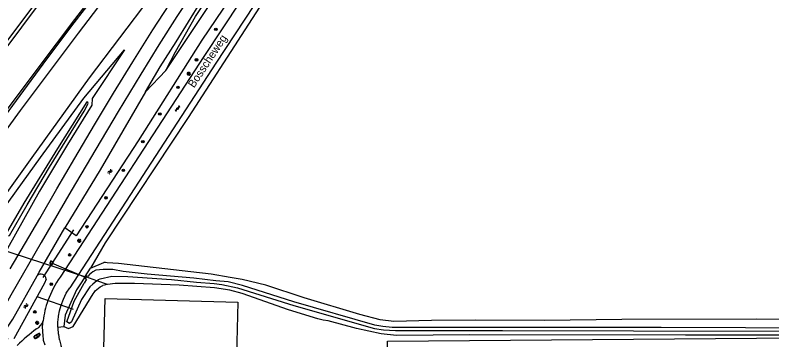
# Model space of a CAD drawing. Extents: x 137999 to 141000, y 397500 to 400501.
# Drawn here: x 138446.7 to 138683.2, y 398816.7 to 398918.2 of the extents above; entities that cross this region are included whole.
import ezdxf

# ---------------------------------------------------------------- set-up
doc = ezdxf.new("R2010")
doc.units = 0
for name, color, linetype in [('gg-anno-openbare ruimte label', 7, 'Continuous'), ('gg-knt-BGT kruinlijn', 7, 'Continuous'), ('gg-knt-bronhoudergrens', 7, 'Continuous'), ('gg-knt-verharding', 7, 'Continuous'), ('gg-knt-verharding nz', 7, 'Continuous'), ('gg-kntw-bovenkant insteek waterloop', 7, 'Continuous'), ('gg-kwrk-duiker nz buis', 7, 'Continuous'), ('gt-symb-boom', 7, 'Continuous'), ('gt-symb-gesloten verharding', 7, 'Continuous'), ('gt-symb-klinker verharding', 7, 'Continuous'), ('gt-symb-lichtmast', 7, 'Continuous'), ('gt-symb-rioolschacht', 7, 'Continuous'), ('gt-symb-watersymbool', 7, 'Continuous'), ('gx-grn-maaiveld', 7, 'Continuous')]:
    doc.layers.add(name, color=color, linetype=linetype)

# ---------------------------------------------------------------- blocks, each defined once
blk = doc.blocks.new('gt0-BOOM')
at = {"layer": 'gt-symb-boom'}
for radius in [0.4, 0.2]:
    blk.add_circle((0, 0), radius, dxfattribs=at)
blk = doc.blocks.new('gt0-GESVH1')
at = {"layer": 'gt-symb-gesloten verharding'}
for p, q in [((-0.99, -0.26), (0.01, 0.24)), ((0.01, -0.26), (-0.99, 0.24)), ((0.01, 0.24), (1.01, -0.26)), ((1.01, 0.24), (0.01, -0.26))]:
    blk.add_line(p, q, dxfattribs=at)
blk = doc.blocks.new('gt0-LMAST')
at = {"layer": 'gt-symb-lichtmast'}
for p, q in [((-0.18, 0.17), (-0.45, 0.44)), ((0, 0.25), (0, 0.62)), ((0.17, 0.17), (0.44, 0.44)), ((-0.25, 0), (-0.63, 0)), ((-0.18, -0.18), (-0.45, -0.45)), ((0, -0.25), (0, -0.63)), ((0.44, -0.45), (0.17, -0.18)), ((0.25, 0), (0.62, 0))]:
    blk.add_line(p, q, dxfattribs=at)
blk.add_circle((0, 0), 0.25, dxfattribs=at)
blk = doc.blocks.new('gt0-WA')
at = {"layer": 'gt-symb-watersymbool'}
for centre, start, end in [((-0.32, 0.02), 28.0725, 151.9275), ((0.43, 0.42), 208.0725, 331.9275), ((-0.32, -0.43), 28.0725, 151.9275), ((0.43, -0.03), 208.0725, 331.9275)]:
    blk.add_arc(centre, 0.425, start, end, dxfattribs=at)
blk = doc.blocks.new('gt0-RS')
at = {"layer": 'gt-symb-rioolschacht'}
blk.add_lwpolyline([(-0.5, -0.5), (0.5, -0.5), (0.5, 0.5), (-0.5, 0.5)], close=True, dxfattribs=at)
blk.add_circle((0, 0), 0.375, dxfattribs=at)
blk = doc.blocks.new('gt0-KL1')
at = {"layer": 'gt-symb-klinker verharding'}
for p, q in [((-1.15, 0.3), (1.15, 0.3)), ((-1, -0.3), (-1, 0.3)), ((-0.5, 0.3), (-0.5, 0.45)), ((0, -0.3), (0, 0.3)), ((0.5, 0.3), (0.5, 0.45)), ((1, -0.3), (1, 0.3)), ((-1.15, -0.3), (1.15, -0.3)), ((-0.5, -0.45), (-0.5, -0.3)), ((0.5, -0.45), (0.5, -0.3))]:
    blk.add_line(p, q, dxfattribs=at)

msp = doc.modelspace()

# ---------------------------------------------------------------- linework, layer by layer
at = {"layer": 'gg-knt-BGT kruinlijn'}
for p, q in [((138497.03, 398909.88), (138504.8, 398922.39)), ((138441.84, 398907.05), (138452.95, 398921.72)), ((138492, 398902.03), (138497.03, 398909.88)), ((138487.49, 398894.21), (138492, 398902.03))]:
    msp.add_line(p, q, dxfattribs=at)
at = {"layer": 'gg-knt-bronhoudergrens'}
msp.add_lwpolyline([(138453.6, 398836.7), (138454.22, 398837.81), (138462.27, 398851.67)], dxfattribs=at)
at = {"layer": 'gg-knt-verharding'}
for p, q in [((138453.68, 398818.43), (138452.83, 398817.95)), ((138453.33, 398817.19), (138454.18, 398817.72))]:
    msp.add_line(p, q, dxfattribs=at)
msp.add_lwpolyline([(138571.8, 399000), (138540.02, 398957.23), (138505.73, 398905.24), (138460.79, 398836.3)], dxfattribs=at)
for centre, radius, start, end in [((138485.43, 398818.82), 30.21, 144.6468, 160.3408), ((138485.42, 398818.82), 30.2, 160.3332, 172.7902), ((138451.65, 398823.67), 3.95, 296.1487, 344.4578), ((138493.04, 398768.15), 65.36, 127.3417, 134.273), ((138453.07, 398817.56), 0.454, 121.3269, 305.4573), ((138453.96, 398818.1), 0.435, 300.0104, 130.3422)]:
    msp.add_arc(centre, radius, start, end, dxfattribs=at)
at = {"layer": 'gg-knt-verharding nz'}
msp.add_lwpolyline([(138456.1, 398815.01), (138455.63, 398816.48), (138455.59, 398816.9), (138455.45, 398817.89), (138455.24, 398820.76), (138455.46, 398822.61)], dxfattribs=at)
at = {"layer": 'gg-kntw-bovenkant insteek waterloop'}
for points in [[(138569.06, 399000), (138567.59, 398998.16), (138559.63, 398990.84), (138557.55, 398988.03), (138505.1, 398910.32), (138485.15, 398878.9), (138465.82, 398849.17), (138462.27, 398851.67)], [(138444.52, 398816.88), (138442.67, 398818.18), (138446.06, 398823.16), (138453.6, 398836.7)], [(138456.41, 398835.69), (138455.87, 398834.38), (138446.37, 398816.98)]]:
    msp.add_lwpolyline(points, dxfattribs=at)
msp.add_arc((138454.79, 398835.61), 1.62, 3.0222, 137.6006, dxfattribs=at)
at = {"layer": 'gg-kwrk-duiker nz buis'}
for p, q in [((138398.36, 398859.43), (138468.99, 398836.26)), ((138455.47, 398836.15), (138465.1, 398851.11)), ((138458.09, 398840.75), (138468.78, 398836.21)), ((138465.02, 398826.16), (138453.59, 398830.17))]:
    msp.add_line(p, q, dxfattribs=at)
at = {"layer": 'gx-grn-maaiveld'}
for p, q in [((138487.49, 398894.21), (138493.8, 398900.86)), ((138470.28, 398839.08), (138474.43, 398840.89)), ((138468.57, 398836.44), (138467.34, 398834.55)), ((138468.85, 398836.34), (138468.57, 398836.44)), ((138472.26, 398835.13), (138468.85, 398836.34)), ((138472.26, 398835.13), (138471.06, 398834.07)), ((138475.64, 398833.94), (138472.26, 398835.13)), ((138475.64, 398833.94), (138474.1, 398833.68)), ((138460.08, 398820.65), (138461.99, 398820.81))]:
    msp.add_line(p, q, dxfattribs=at)
for points in [[(138501.93, 398981.31), (138473.35, 398946.25), (138454.53, 398922.28), (138436.97, 398898.82), (138420.73, 398876.2), (138406.46, 398855.7), (138389.11, 398830.38), (138374.16, 398808.03), (138357.61, 398782.41), (138337.09, 398749.31), (138322.84, 398725.57), (138306.14, 398696.86), (138294.74, 398676.9)], [(138511.96, 398975.93), (138501.93, 398963.57), (138488.51, 398946.76), (138477.26, 398932.48), (138465.23, 398916.8), (138454.1, 398902.02), (138442.39, 398886.25), (138431.73, 398871.47), (138423.79, 398860.21), (138409, 398839.04), (138400.22, 398826.26), (138391.06, 398812.74), (138383.32, 398801.2), (138369.25, 398779.46), (138351.53, 398751.27), (138335.99, 398725.63), (138320.07, 398698.46), (138305.76, 398673.14), (138304.77, 398671.25)], [(138305.51, 398670.84), (138318.83, 398694.74), (138335.5, 398723.24), (138353.01, 398752.39), (138371.79, 398782.1), (138383.87, 398800.92), (138391.62, 398812.28), (138401.25, 398826.65), (138409.13, 398838.16), (138419.71, 398853.23), (138427.79, 398864.74), (138439.06, 398880.6), (138447.18, 398891.55), (138456.66, 398904.44), (138465.19, 398915.76), (138474.86, 398928.37), (138485.07, 398941.42), (138495.05, 398953.91), (138502.76, 398963.65), (138512.45, 398975.67)], [(138515.33, 398974.12), (138508.14, 398965.28), (138499.1, 398954.3), (138490.91, 398943.97), (138482.68, 398933.64), (138474.18, 398922.64), (138466.42, 398912.51), (138457.95, 398901.32), (138448.31, 398888.42), (138439.64, 398876.56), (138431.08, 398864.56), (138422.11, 398851.79), (138414.01, 398840.2), (138403.68, 398825.33), (138393.35, 398810.12), (138386.42, 398799.63), (138373.52, 398779.54), (138349.79, 398741.53), (138323.85, 398697.93), (138308.01, 398669.51)], [(138445.2, 398838.89), (138454.46, 398854.65), (138459.76, 398863.94), (138465.34, 398873.45), (138471.5, 398883.92), (138477.49, 398893.83), (138483.55, 398903.63), (138489.79, 398913.61), (138496.63, 398924.24), (138502.81, 398933.7), (138510, 398944), (138515.54, 398951.76), (138520.63, 398958.64), (138518.24, 398960.23), (138506.25, 398945.82), (138488.86, 398923.75), (138469.91, 398898.56), (138451.9, 398873.72), (138435.15, 398850.39)], [(138536.45, 398944.23), (138509.39, 398903.14), (138463.79, 398832.99)], [(138538.48, 398944.62), (138500.76, 398886.17), (138474.86, 398846.97), (138470.28, 398839.08)], [(138493.8, 398900.86), (138496.8, 398906.75), (138503.12, 398917.76), (138509.47, 398927.48), (138512.14, 398931.65), (138515.98, 398937.39), (138519.12, 398939.39)], [(138493.8, 398900.86), (138508.22, 398922.45), (138519.12, 398939.39)], [(138510.93, 398938.07), (138503.76, 398927.52), (138497.3, 398917.73), (138491.67, 398908.92), (138485.99, 398899.71), (138478.97, 398888.11), (138471.93, 398876.34), (138464.28, 398863.27), (138454.82, 398847.09), (138445.4, 398830.65), (138437.66, 398816.93), (138433.16, 398808.86)], [(138319.3, 398663.29), (138320.07, 398664.67), (138327.85, 398678.47), (138336.64, 398694.05), (138345.76, 398709.35), (138356.08, 398726.35), (138365.52, 398742.12), (138375.87, 398758.54), (138387.56, 398776.99), (138398.34, 398793.59), (138411.58, 398813.08), (138429.8, 398839.31), (138439.07, 398852.14), (138454.7, 398873.68), (138468.19, 398892.19), (138480.86, 398907.3), (138470.85, 398892.13), (138470.73, 398890.07), (138463.09, 398877.71), (138454.36, 398863.15), (138444.37, 398845.19), (138441.69, 398841)], [(138487.49, 398894.21), (138473.34, 398869.79), (138462.27, 398851.67)], [(138468.29, 398888.14), (138469.6, 398890.53), (138469.4, 398890.9), (138469.15, 398891.04), (138459.97, 398876.54), (138449.41, 398859.44), (138443.92, 398849.96), (138444.13, 398849.45), (138444.45, 398849.24), (138444.92, 398849.29), (138450.49, 398858.84), (138457.51, 398870.62), (138468.29, 398888.14)], [(138468.57, 398836.44), (138468.57, 398836.44), (138470.28, 398839.08)], [(138709.84, 398822.76), (138678.4, 398823.13), (138636.32, 398823.04), (138612.17, 398822.78), (138590.49, 398822.81), (138576.79, 398822.72), (138565.07, 398822.41), (138560.83, 398822.9), (138554.47, 398824.65), (138537.09, 398829.84), (138525.08, 398833.78), (138517.68, 398835.54), (138513.96, 398836.2), (138507.98, 398837.26), (138501.66, 398837.9), (138478.99, 398840.51), (138475.46, 398840.79)], [(138701.3, 398820.36), (138648.59, 398820.54), (138601.81, 398820.59), (138564.58, 398820.55), (138561.57, 398820.81), (138559.12, 398821.26), (138533.82, 398828.59), (138517.77, 398833.64), (138513.32, 398834.83), (138509.43, 398835.18), (138502.58, 398835.94), (138487.95, 398837.26), (138480.53, 398838.02), (138477.28, 398838.65), (138474.24, 398838.71), (138471.96, 398838.51), (138471.02, 398837.98), (138470.01, 398837.16), (138469.47, 398836.51), (138469.08, 398836.73), (138468.85, 398836.34)], [(138792.19, 398837.02), (138789.69, 398836.25), (138782.84, 398833.81), (138771.64, 398830.41), (138752.15, 398825.35), (138742.61, 398823), (138723.68, 398818.94), (138718.46, 398818.15), (138656.21, 398818.1), (138588.8, 398818.22), (138565.84, 398818.04), (138561.1, 398818.52), (138553.4, 398820.2), (138544.56, 398822.59), (138543.01, 398822.89), (138541.31, 398823.22), (138532.12, 398826.1), (138517.7, 398831.22), (138513.81, 398832.21), (138509.07, 398832.97), (138497.98, 398833.8), (138484.06, 398834.27), (138477.98, 398834.33), (138475.64, 398833.94)], [(138467.34, 398834.55), (138465.9, 398832.34), (138462.4, 398824.36), (138461.99, 398820.81)], [(138471.06, 398834.07), (138470.11, 398833.24), (138467.46, 398829.32), (138464.32, 398822.3), (138463.68, 398821.8), (138462.86, 398822.35), (138465.19, 398828.82), (138468.32, 398834.43)], [(138468.85, 398836.34), (138468.78, 398836.21), (138468.64, 398835.94), (138469.02, 398835.68), (138468.32, 398834.43)], [(138472.26, 398835.13), (138472.5, 398835.34), (138472.8, 398835.51), (138473.33, 398835.81), (138476.93, 398836.6), (138481.95, 398836.52), (138495.6, 398835.51), (138503.35, 398834.75), (138508.93, 398834.25), (138511.34, 398833.94), (138516.16, 398832.9), (138533.76, 398827.4), (138559.06, 398820.26), (138561.84, 398819.84), (138565.58, 398819.59), (138598.97, 398819.6), (138639.89, 398819.52), (138700.99, 398819.36)], [(138461.07, 398827.54), (138461.8, 398829.45), (138462.71, 398831.27), (138463.79, 398832.99)], [(138461.99, 398820.81), (138463.44, 398820.22), (138464.9, 398820.9), (138471.12, 398831.07), (138471.38, 398831.5), (138471.7, 398832.05), (138473.25, 398833.26), (138474.1, 398833.68)], [(138474.83, 398829.58), (138516.36, 398828.47), (138515.47, 398795.14), (138473.99, 398798.55), (138474.83, 398829.58)], [(138460.08, 398820.65), (138460.08, 398822.05), (138460.08, 398822.15), (138460.09, 398822.23), (138460.24, 398823.86), (138460.25, 398823.98), (138460.27, 398824.04), (138460.57, 398825.73), (138460.58, 398825.78), (138460.59, 398825.8), (138461.07, 398827.54)], [(138460.08, 398820.65), (138460.08, 398820.32), (138460.22, 398818.61), (138460.23, 398818.49), (138460.25, 398818.41), (138460.53, 398816.78), (138460.55, 398816.69), (138460.56, 398816.64), (138461.01, 398814.98), (138461.02, 398814.92), (138461.04, 398814.89), (138461.65, 398813.2)], [(138563.1, 398809.75), (138563.04, 398816.25), (138729.56, 398817.68), (138757.71, 398817.87), (138757.64, 398822.29), (138789.96, 398822.44), (138789.89, 398809.11), (138793.97, 398809.15), (138794.28, 398758.6), (138730.04, 398758.64), (138642.09, 398757.88), (138642.08, 398758.73), (138570.05, 398758.11), (138570.04, 398759.5), (138563.46, 398759.45), (138563.35, 398772.44), (138552.04, 398772.34), (138551.72, 398809.65), (138563.1, 398809.75)]]:
    msp.add_lwpolyline(points, dxfattribs=at)
msp.add_arc((138474.17, 398833.22), 7.68, 80.3193, 88.0839, dxfattribs=at)

# ---------------------------------------------------------------- block references
at = {"layer": 'gt-symb-boom'}
for p in [(138509.44, 398913.76), (138503.38, 398904.23), (138497.61, 398895.61), (138491.96, 398887.27), (138486.64, 398878.64), (138480.55, 398869.66), (138475.13, 398861.1), (138469.18, 398852.04), (138463.77, 398843.23), (138458.04, 398834.08), (138452.88, 398825.42)]:
    msp.add_blockref('gt0-BOOM', p, dxfattribs=at)
at = {"layer": 'gt-symb-gesloten verharding', "rotation": 51.98433951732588}
msp.add_blockref('gt0-GESVH1', (138497.47, 398888.96), dxfattribs=at)
at = {"layer": 'gt-symb-klinker verharding', "rotation": -147.86710414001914}
msp.add_blockref('gt0-KL1', (138453.56, 398817.86), dxfattribs=at)
at = {"layer": 'gt-symb-lichtmast'}
for p in [(138500.96, 398899.88), (138466.77, 398847.68), (138453.63, 398822.02)]:
    msp.add_blockref('gt0-LMAST', p, dxfattribs=at)
at = {"layer": 'gt-symb-rioolschacht', "rotation": 64.46026718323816}
msp.add_blockref('gt0-RS', (138458.1, 398840.76), dxfattribs=at)
at = {"layer": 'gt-symb-watersymbool'}
for p, rotation in [((138476.35, 398869.21), 57.70905164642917), ((138450.07, 398827.22), 57.454106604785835)]:
    msp.add_blockref('gt0-WA', p, dxfattribs=dict(at, rotation=rotation))

# ---------------------------------------------------------------- texts
at = {"layer": 'gg-anno-openbare ruimte label'}
msp.add_text('Bosscheweg', height=2.5, rotation=56.5, dxfattribs=at).set_placement((138502.62, 398895.25))

doc.saveas('drawing.dxf')
